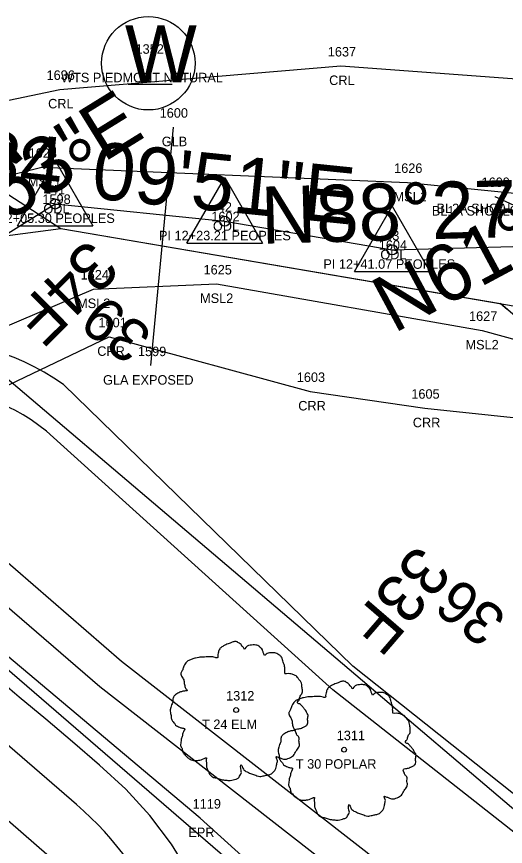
# Model space of a CAD drawing. Extents: x 1812113 to 1819860, y 1177290 to 1181185.
# Drawn here: x 1813798.2 to 1813849.5, y 1178667.1 to 1178754.3 of the extents above; entities that cross this region are included whole.
import ezdxf

# ---------------------------------------------------------------- set-up
doc = ezdxf.new("R2010")
doc.units = 0
for name, color, linetype in [('RD_DTM_BkLn1', 7, 'Continuous'), ('RD_EX_DV_Prop', 7, 'Continuous'), ('RD_EX_H2O', 7, 'Continuous'), ('RD_EX_H2O_txCode', 7, 'Continuous'), ('RD_EX_Misc', 7, 'Continuous'), ('RD_EX_Misc_txCode', 7, 'Continuous'), ('RD_EX_Road', 7, 'Continuous'), ('RD_EX_Road_txCode', 7, 'Continuous'), ('RD_EX_RW', 7, 'Continuous'), ('RD_EX_UT', 7, 'Continuous'), ('RD_EX_UT_txCode', 7, 'Continuous'), ('RD_EX_VEG', 7, 'Continuous'), ('RD_EX_VEG_txCode', 7, 'Continuous'), ('RD_HC_CL', 7, 'Continuous'), ('RD_HC_Data', 7, 'Continuous'), ('RD_HC_txCode', 7, 'Continuous'), ('RD_PD_ALT1_LnLine', 7, 'Continuous'), ('RD_PD_ALT1_TnTmp', 7, 'Continuous'), ('RD_PD_ALT1_TrvlWay', 7, 'Continuous'), ('RD_PD_CstnLmt', 7, 'Continuous'), ('RD_PD_DR_ErosCtrl', 7, 'Continuous'), ('RD_PD_GR', 7, 'Continuous'), ('RD_PD_PatLn1', 7, 'Continuous'), ('RD_PD_RW', 7, 'Continuous'), ('RD_Sketch7', 7, 'Continuous'), ('RD_SMD_Locator', 7, 'Continuous'), ('RD_SMD_Misc', 7, 'Continuous')]:
    doc.layers.add(name, color=color, linetype=linetype)

msp = doc.modelspace()

# ---------------------------------------------------------------- linework, layer by layer
at = {"layer": 'RD_DTM_BkLn1'}
msp.add_line((1813848.444, 1178735.384), (1813869.763, 1178725.59), dxfattribs=at)
at = {"layer": 'RD_EX_DV_Prop'}
for p, q in [((1813781.836, 1178729.192), (1813802.812, 1178732.04)), ((1813802.812, 1178732.04), (1813850.785, 1178723.835)), ((1813854.673, 1178667.319), (1813781.836, 1178729.192))]:
    msp.add_line(p, q, dxfattribs=at)
at = {"layer": 'RD_EX_H2O'}
for points in [[(1813767.831, 1178739.336), (1813802.696, 1178746.648), (1813832.241, 1178749.109), (1813880.122, 1178745.593), (1813913.043, 1178737.891)], [(1813747.032, 1178677.406), (1813754.345, 1178684.796), (1813763.952, 1178688.126), (1813782.123, 1178708.315), (1813807.886, 1178720.632), (1813829.016, 1178714.89), (1813841.058, 1178713.127), (1813882.921, 1178708.729), (1813906.373, 1178716.286)]]:
    msp.add_lwpolyline(points, dxfattribs=at)
at = {"layer": 'RD_EX_Misc'}
for points in [[(1813573.261, 1178698.609), (1813581.176, 1178685.417), (1813588.271, 1178683.03), (1813621.867, 1178683.405), (1813652.093, 1178681.47), (1813685.623, 1178688.184), (1813723.849, 1178690.459), (1813735.911, 1178692.91), (1813768.219, 1178723.128), (1813784.539, 1178734.4), (1813800.789, 1178738.457), (1813839.236, 1178736.87), (1813863.895, 1178734.392), (1813884.494, 1178732.558), (1813903.275, 1178733.231)], [(1813591.145, 1178668.772), (1813628.984, 1178667.844), (1813655.761, 1178668.83), (1813686.954, 1178670.41), (1813726.51, 1178669.36), (1813738.941, 1178670.711), (1813788.676, 1178718.193), (1813806.253, 1178725.658), (1813819.179, 1178726.191), (1813847.084, 1178721.307), (1813860.38, 1178717.648), (1813871.967, 1178724.247), (1813883.921, 1178723.481), (1813902.674, 1178722.415)]]:
    msp.add_lwpolyline(points, dxfattribs=at)
at = {"layer": 'RD_EX_Road'}
msp.add_lwpolyline([(1814076.449, 1178427.399), (1814038.861, 1178461.867), (1814001.829, 1178496.617), (1813965.148, 1178531.537), (1813928.085, 1178567.095), (1813892.01, 1178601.225), (1813854.538, 1178636.515), (1813817.438, 1178670.033), (1813779.867, 1178701.638)], dxfattribs=at)
at = {"layer": 'RD_EX_RW'}
msp.add_line((1813768.43, 1178754.211), (1813802.812, 1178732.04), dxfattribs=at)
at = {"layer": 'RD_EX_UT'}
for p, q in [((1813809.873, 1178747.186), (1813814.502, 1178747.186)), ((1813812.259, 1178717.603), (1813814.643, 1178742.673))]:
    msp.add_line(p, q, dxfattribs=at)
msp.add_circle((1813812.001, 1178749.394), 4.908, dxfattribs=at)
at = {"layer": 'RD_EX_VEG'}
for centre, radius in [((1813821.238, 1178681.396), 0.25), ((1813821.225, 1178681.377), 0.0001), ((1813832.586, 1178677.226), 0.25), ((1813832.574, 1178677.207), 0.0001)]:
    msp.add_circle(centre, radius, dxfattribs=at)
for points in [[(1813821.37, 1178688.563), (1813821.07, 1178688.588), (1813820.745, 1178688.488), (1813820.495, 1178688.388), (1813820.27, 1178688.313), (1813820.045, 1178688.213), (1813819.745, 1178688.038), (1813819.52, 1178687.838), (1813819.395, 1178687.588), (1813819.345, 1178687.363), (1813819.295, 1178687.088), (1813819.295, 1178686.913), (1813819.171, 1178686.888), (1813819.021, 1178686.913), (1813818.771, 1178686.988), (1813818.521, 1178686.988), (1813818.271, 1178686.988), (1813817.921, 1178686.963), (1813817.571, 1178686.963), (1813817.296, 1178686.913), (1813816.971, 1178686.864), (1813816.597, 1178686.739), (1813816.247, 1178686.614), (1813815.947, 1178686.364), (1813815.697, 1178685.889), (1813815.572, 1178685.539), (1813815.422, 1178685.289), (1813815.572, 1178684.839), (1813815.747, 1178684.49), (1813815.772, 1178684.29), (1813815.847, 1178683.865), (1813815.947, 1178683.64), (1813816.072, 1178683.44), (1813815.997, 1178683.415), (1813815.622, 1178683.365), (1813815.322, 1178683.265), (1813814.897, 1178683.04), (1813814.672, 1178682.815), (1813814.572, 1178682.49), (1813814.548, 1178682.141), (1813814.448, 1178681.941), (1813814.373, 1178681.666), (1813814.348, 1178681.591), (1813814.298, 1178681.266), (1813814.398, 1178680.816), (1813814.423, 1178680.466), (1813814.548, 1178680.241), (1813814.697, 1178680.067), (1813814.872, 1178679.817), (1813815.272, 1178679.592), (1813815.597, 1178679.492), (1813815.797, 1178679.467), (1813815.622, 1178678.967), (1813815.572, 1178678.617), (1813815.447, 1178678.217), (1813815.447, 1178678.142), (1813815.397, 1178677.668), (1813815.547, 1178677.343), (1813815.622, 1178676.968), (1813815.797, 1178676.743), (1813816.072, 1178676.443), (1813816.397, 1178676.218), (1813816.897, 1178676.093), (1813817.296, 1178676.118), (1813817.871, 1178676.293), (1813818.121, 1178676.368), (1813818.096, 1178676.193), (1813818.121, 1178675.818), (1813818.121, 1178675.394), (1813818.271, 1178675.069), (1813818.371, 1178674.794), (1813818.521, 1178674.544), (1813818.846, 1178674.319), (1813819.245, 1178674.244), (1813819.67, 1178674.094), (1813820.12, 1178674.019), (1813820.62, 1178673.994), (1813821.22, 1178674.144), (1813821.494, 1178674.269), (1813821.594, 1178674.444), (1813821.794, 1178674.819), (1813821.744, 1178675.044), (1813821.769, 1178675.643), (1813821.869, 1178675.468), (1813822.044, 1178675.119), (1813822.544, 1178674.819), (1813822.944, 1178674.644), (1813823.419, 1178674.494), (1813823.719, 1178674.419), (1813824.193, 1178674.494), (1813824.568, 1178674.569), (1813824.943, 1178674.694), (1813825.243, 1178674.969), (1813825.418, 1178675.244), (1813825.468, 1178675.518), (1813825.543, 1178675.893), (1813825.593, 1178676.068)], [(1813825.593, 1178676.068), (1813825.518, 1178676.243), (1813825.468, 1178676.493), (1813825.543, 1178676.468), (1813825.718, 1178676.418), (1813825.993, 1178676.293), (1813826.217, 1178676.218), (1813826.542, 1178676.243), (1813826.817, 1178676.343), (1813827.267, 1178676.618), (1813827.542, 1178677.093), (1813827.817, 1178677.493), (1813827.892, 1178677.817), (1813827.842, 1178678.042), (1813827.817, 1178678.542), (1813827.617, 1178678.792), (1813827.567, 1178678.917), (1813827.467, 1178679.317), (1813827.542, 1178679.367), (1813827.817, 1178679.417), (1813828.192, 1178679.542), (1813828.466, 1178679.667), (1813828.691, 1178679.842), (1813828.766, 1178680.067), (1813828.741, 1178680.466), (1813828.791, 1178680.866), (1813828.716, 1178681.016), (1813828.616, 1178681.166), (1813828.541, 1178681.366), (1813828.391, 1178681.516), (1813828.292, 1178681.666), (1813828.192, 1178681.766), (1813828.067, 1178681.916), (1813827.892, 1178682.041), (1813827.742, 1178682.091), (1813827.692, 1178682.241), (1813827.842, 1178682.44), (1813827.892, 1178682.54), (1813827.917, 1178682.765), (1813828.142, 1178683.115), (1813828.192, 1178683.515), (1813828.142, 1178683.94), (1813828.092, 1178684.215), (1813827.942, 1178684.49), (1813827.742, 1178684.739), (1813827.617, 1178684.914), (1813827.442, 1178685.039), (1813827.117, 1178685.164), (1813826.867, 1178685.214), (1813826.517, 1178685.214), (1813826.317, 1178685.264), (1813826.342, 1178685.314), (1813826.342, 1178685.464), (1813826.342, 1178685.739), (1813826.267, 1178686.189), (1813826.117, 1178686.689), (1813826.117, 1178686.714), (1813826.017, 1178686.963), (1813825.793, 1178687.163), (1813825.618, 1178687.263), (1813825.418, 1178687.388), (1813825.168, 1178687.413), (1813824.868, 1178687.413), (1813824.593, 1178687.363), (1813824.393, 1178687.263), (1813824.218, 1178687.138), (1813824.143, 1178687.288), (1813824.043, 1178687.588), (1813823.993, 1178687.738), (1813823.843, 1178687.913), (1813823.619, 1178688.113), (1813823.169, 1178688.238), (1813822.544, 1178688.163), (1813822.244, 1178687.963), (1813822.094, 1178687.788), (1813822.044, 1178687.913), (1813821.844, 1178688.113), (1813821.744, 1178688.288), (1813821.569, 1178688.413), (1813821.42, 1178688.513), (1813821.32, 1178688.563)], [(1813832.718, 1178684.393), (1813832.418, 1178684.418), (1813832.094, 1178684.318), (1813831.844, 1178684.218), (1813831.619, 1178684.143), (1813831.394, 1178684.043), (1813831.094, 1178683.868), (1813830.869, 1178683.668), (1813830.744, 1178683.418), (1813830.694, 1178683.193), (1813830.644, 1178682.918), (1813830.644, 1178682.743), (1813830.519, 1178682.718), (1813830.369, 1178682.743), (1813830.119, 1178682.818), (1813829.869, 1178682.818), (1813829.62, 1178682.818), (1813829.27, 1178682.793), (1813828.92, 1178682.793), (1813828.645, 1178682.743), (1813828.32, 1178682.694), (1813827.945, 1178682.569), (1813827.595, 1178682.444), (1813827.296, 1178682.194), (1813827.046, 1178681.719), (1813826.921, 1178681.369), (1813826.771, 1178681.119), (1813826.921, 1178680.669), (1813827.096, 1178680.32), (1813827.121, 1178680.12), (1813827.196, 1178679.695), (1813827.296, 1178679.47), (1813827.421, 1178679.27), (1813827.346, 1178679.245), (1813826.971, 1178679.195), (1813826.671, 1178679.095), (1813826.246, 1178678.87), (1813826.021, 1178678.645), (1813825.921, 1178678.32), (1813825.896, 1178677.971), (1813825.796, 1178677.771), (1813825.721, 1178677.496), (1813825.696, 1178677.421), (1813825.646, 1178677.096), (1813825.746, 1178676.646), (1813825.771, 1178676.296), (1813825.896, 1178676.071), (1813826.046, 1178675.897), (1813826.221, 1178675.647), (1813826.621, 1178675.422), (1813826.946, 1178675.322), (1813827.146, 1178675.297), (1813826.971, 1178674.797), (1813826.921, 1178674.447), (1813826.796, 1178674.047), (1813826.796, 1178673.972), (1813826.746, 1178673.498), (1813826.896, 1178673.173), (1813826.971, 1178672.798), (1813827.146, 1178672.573), (1813827.421, 1178672.273), (1813827.745, 1178672.048), (1813828.245, 1178671.923), (1813828.645, 1178671.948), (1813829.22, 1178672.123), (1813829.47, 1178672.198), (1813829.445, 1178672.023), (1813829.47, 1178671.648), (1813829.47, 1178671.224), (1813829.62, 1178670.899), (1813829.72, 1178670.624), (1813829.869, 1178670.374), (1813830.194, 1178670.149), (1813830.594, 1178670.074), (1813831.019, 1178669.924), (1813831.469, 1178669.849), (1813831.969, 1178669.824), (1813832.568, 1178669.974), (1813832.843, 1178670.099), (1813832.943, 1178670.274), (1813833.143, 1178670.649), (1813833.093, 1178670.874), (1813833.118, 1178671.473), (1813833.218, 1178671.298), (1813833.393, 1178670.949), (1813833.893, 1178670.649), (1813834.293, 1178670.474), (1813834.767, 1178670.324), (1813835.067, 1178670.249), (1813835.542, 1178670.324), (1813835.917, 1178670.399), (1813836.292, 1178670.524), (1813836.592, 1178670.799), (1813836.766, 1178671.074), (1813836.816, 1178671.348), (1813836.891, 1178671.723), (1813836.941, 1178671.898)], [(1813836.941, 1178671.898), (1813836.866, 1178672.073), (1813836.816, 1178672.323), (1813836.891, 1178672.298), (1813837.066, 1178672.248), (1813837.341, 1178672.123), (1813837.566, 1178672.048), (1813837.891, 1178672.073), (1813838.166, 1178672.173), (1813838.616, 1178672.448), (1813838.891, 1178672.923), (1813839.165, 1178673.323), (1813839.24, 1178673.647), (1813839.19, 1178673.872), (1813839.165, 1178674.372), (1813838.965, 1178674.622), (1813838.915, 1178674.747), (1813838.816, 1178675.147), (1813838.891, 1178675.197), (1813839.165, 1178675.247), (1813839.54, 1178675.372), (1813839.815, 1178675.497), (1813840.04, 1178675.672), (1813840.115, 1178675.897), (1813840.09, 1178676.296), (1813840.14, 1178676.696), (1813840.065, 1178676.846), (1813839.965, 1178676.996), (1813839.89, 1178677.196), (1813839.74, 1178677.346), (1813839.64, 1178677.496), (1813839.54, 1178677.596), (1813839.415, 1178677.746), (1813839.24, 1178677.871), (1813839.09, 1178677.921), (1813839.04, 1178678.071), (1813839.19, 1178678.27), (1813839.24, 1178678.37), (1813839.265, 1178678.595), (1813839.49, 1178678.945), (1813839.54, 1178679.345), (1813839.49, 1178679.77), (1813839.44, 1178680.045), (1813839.29, 1178680.32), (1813839.09, 1178680.569), (1813838.965, 1178680.744), (1813838.791, 1178680.869), (1813838.466, 1178680.994), (1813838.216, 1178681.044), (1813837.866, 1178681.044), (1813837.666, 1178681.094), (1813837.691, 1178681.144), (1813837.691, 1178681.294), (1813837.691, 1178681.569), (1813837.616, 1178682.019), (1813837.466, 1178682.519), (1813837.466, 1178682.544), (1813837.366, 1178682.793), (1813837.141, 1178682.993), (1813836.966, 1178683.093), (1813836.766, 1178683.218), (1813836.517, 1178683.243), (1813836.217, 1178683.243), (1813835.942, 1178683.193), (1813835.742, 1178683.093), (1813835.567, 1178682.968), (1813835.492, 1178683.118), (1813835.392, 1178683.418), (1813835.342, 1178683.568), (1813835.192, 1178683.743), (1813834.967, 1178683.943), (1813834.517, 1178684.068), (1813833.893, 1178683.993), (1813833.593, 1178683.793), (1813833.443, 1178683.618), (1813833.393, 1178683.743), (1813833.193, 1178683.943), (1813833.093, 1178684.118), (1813832.918, 1178684.243), (1813832.768, 1178684.343), (1813832.668, 1178684.393)]]:
    msp.add_spline(points, degree=3, dxfattribs=at)
at = {"layer": 'RD_HC_CL'}
for p, q in [((1813785.202, 1178724.075), (1813802.213, 1178734.602)), ((1813802.213, 1178734.602), (1813820.035, 1178732.781)), ((1813820.035, 1178732.781), (1813837.634, 1178729.785)), ((1813837.634, 1178729.785), (1813857.382, 1178730.318)), ((1813850.516, 1178623.797), (1813755.38, 1178705.862))]:
    msp.add_line(p, q, dxfattribs=at)
at = {"layer": 'RD_HC_Data'}
for p, q in [((1813798.242, 1178732.31), (1813802.214, 1178739.189)), ((1813802.214, 1178739.189), (1813806.183, 1178732.31)), ((1813816.064, 1178730.488), (1813820.036, 1178737.368)), ((1813820.036, 1178737.368), (1813824.004, 1178730.488)), ((1813833.664, 1178727.492), (1813837.636, 1178734.372)), ((1813837.636, 1178734.372), (1813841.604, 1178727.492)), ((1813798.242, 1178732.31), (1813806.183, 1178732.31)), ((1813816.064, 1178730.488), (1813824.004, 1178730.488)), ((1813833.664, 1178727.492), (1813841.604, 1178727.492))]:
    msp.add_line(p, q, dxfattribs=at)
for centre in [(1813802.213, 1178734.602), (1813820.035, 1178732.781), (1813837.634, 1178729.785)]:
    msp.add_circle(centre, 0.529, dxfattribs=at)
at = {"layer": 'RD_PD_ALT1_LnLine'}
for p, q in [((1813781.836, 1178729.192), (1813802.812, 1178732.04)), ((1813802.812, 1178732.04), (1813849.018, 1178724.137)), ((1813854.673, 1178667.319), (1813781.836, 1178729.192)), ((1813849.018, 1178724.137), (1813849.716, 1178723.535))]:
    msp.add_line(p, q, dxfattribs=at)
at = {"layer": 'RD_PD_ALT1_TrvlWay'}
msp.add_line((1813855.7, 1178635.172), (1813779.98, 1178700.49), dxfattribs=at)
at = {"layer": 'RD_PD_CstnLmt'}
for p, q in [((1813831.386, 1178683.534), (1813802.048, 1178710.053)), ((1813870.713, 1178652.576), (1813831.386, 1178683.534))]:
    msp.add_line(p, q, dxfattribs=at)
msp.add_arc((1813788.637, 1178695.216), 20, 47.88964, 139.21843, dxfattribs=at)
at = {"layer": 'RD_PD_DR_ErosCtrl'}
for p, q in [((1813833.516, 1178686.004), (1813803.068, 1178715.63)), ((1813872.683, 1178654.86), (1813833.516, 1178686.004))]:
    msp.add_line(p, q, dxfattribs=at)
msp.add_arc((1813788.637, 1178695.216), 25, 54.74185, 139.21843, dxfattribs=at)
at = {"layer": 'RD_PD_GR'}
for p, q in [((1813783.246, 1178704.276), (1813806.909, 1178683.864)), ((1813806.909, 1178683.864), (1813846.352, 1178653.136))]:
    msp.add_line(p, q, dxfattribs=at)
at = {"layer": 'RD_PD_PatLn1'}
for p, q in [((1813809.195, 1178686.515), (1813785.532, 1178706.926)), ((1813848.639, 1178655.787), (1813809.195, 1178686.515))]:
    msp.add_line(p, q, dxfattribs=at)
at = {"layer": 'RD_PD_RW'}
msp.add_line((1813877.921, 1178699.206), (1813849.018, 1178724.137), dxfattribs=at)
at = {"layer": 'RD_Sketch7'}
msp.add_line((1813804.452, 1178671.456), (1813759.299, 1178710.406), dxfattribs=at)
msp.add_lwpolyline([(1813816.387, 1178664.101), (1813814.425, 1178667.296), (1813812.168, 1178670.297), (1813809.633, 1178673.074), (1813806.855, 1178675.611), (1813804.027, 1178678.042), (1813801.221, 1178680.423), (1813798.44, 1178682.762), (1813795.686, 1178685.068)], dxfattribs=at)
msp.add_arc((1813781.591, 1178644.954), 35, 303.51678, 49.21843, dxfattribs=at)
at = {"layer": 'RD_SMD_Locator'}
for centre in [(1813832.241, 1178749.109), (1813802.696, 1178746.648), (1813814.643, 1178742.673), (1813800.789, 1178738.457), (1813839.236, 1178736.87), (1813848.444, 1178735.384), (1813802.213, 1178734.602), (1813802.213, 1178734.602), (1813820.035, 1178732.781), (1813820.035, 1178732.781), (1813837.634, 1178729.785), (1813837.634, 1178729.785), (1813806.253, 1178725.658), (1813819.179, 1178726.191), (1813847.084, 1178721.307), (1813807.886, 1178720.632), (1813812.259, 1178717.603), (1813829.016, 1178714.89), (1813841.058, 1178713.127), (1813817.438, 1178670.033)]:
    msp.add_circle(centre, 0.001, dxfattribs=at)

# ---------------------------------------------------------------- texts
at = {"layer": 'RD_EX_H2O_txCode'}
for s, p in [('1637', (1813830.87, 1178750.109)), ('1636', (1813801.303, 1178747.648)), ('CRL', (1813831.012, 1178747.109)), ('CRL', (1813801.468, 1178744.648)), ('1598', (1813800.867, 1178734.602)), ('ODL', (1813800.969, 1178733.602)), ('1602', (1813818.625, 1178732.781)), ('ODL', (1813818.79, 1178731.781)), ('1604', (1813836.225, 1178729.785)), ('ODL', (1813836.39, 1178728.785)), ('1601', (1813806.76, 1178721.632)), ('CRR', (1813806.634, 1178718.632)), ('1603', (1813827.607, 1178715.89)), ('1605', (1813839.649, 1178714.127)), ('CRR', (1813827.764, 1178712.89)), ('CRR', (1813839.806, 1178711.127))]:
    msp.add_text(s, height=1, dxfattribs=at).set_placement(p)
at = {"layer": 'RD_EX_Misc_txCode'}
for s, p in [('1623', (1813799.419, 1178739.457)), ('1626', (1813837.842, 1178737.87)), ('MSL1', (1813799.333, 1178736.457)), ('MSL1', (1813837.779, 1178734.87)), ('1624', (1813804.883, 1178726.658)), ('1625', (1813817.809, 1178727.191)), ('MSL2', (1813817.439, 1178724.191)), ('MSL2', (1813804.513, 1178723.658)), ('1627', (1813845.714, 1178722.307)), ('MSL2', (1813845.344, 1178719.307))]:
    msp.add_text(s, height=1, dxfattribs=at).set_placement(p)
at = {"layer": 'RD_EX_Road_txCode'}
for s, p in [('1119', (1813816.659, 1178671.033)), ('EPR', (1813816.21, 1178668.033))]:
    msp.add_text(s, height=1, dxfattribs=at).set_placement(p)
at = {"layer": 'RD_EX_UT'}
msp.add_text('W', height=6, dxfattribs=at).set_placement((1813809.537, 1178747.393))
at = {"layer": 'RD_EX_UT_txCode'}
for s, p in [('1352', (1813810.655, 1178750.394)), ('WTS PIEDMONT NATURAL', (1813802.828, 1178747.394)), ('1600', (1813813.194, 1178743.673)), ('GLB', (1813813.414, 1178740.673)), ('1599', (1813810.912, 1178718.603)), ('GLA EXPOSED', (1813807.243, 1178715.603))]:
    msp.add_text(s, height=1, dxfattribs=at).set_placement(p)
at = {"layer": 'RD_EX_VEG_txCode'}
for s, p in [('1312', (1813820.175, 1178682.396)), ('T 24 ELM', (1813817.647, 1178679.396)), ('1311', (1813831.807, 1178678.226)), ('T 30 POPLAR', (1813827.508, 1178675.226))]:
    msp.add_text(s, height=1, dxfattribs=at).set_placement(p)
at = {"layer": 'RD_HC_txCode'}
for s, p in [('41', (1813801.764, 1178735.602)), ('42', (1813819.302, 1178733.781)), ('PI 12+05.30 PEOPLES', (1813794.615, 1178732.602)), ('PI 12+23.21 PEOPLES', (1813813.121, 1178730.781)), ('43', (1813836.902, 1178730.785)), ('PI 12+41.07 PEOPLES', (1813830.398, 1178727.785))]:
    msp.add_text(s, height=1, dxfattribs=at).set_placement(p)
at = {"layer": 'RD_PD_ALT1_TnTmp'}
for s, rotation, p in [('N61%%d46\'05"E', 28.23186, (1813837.794, 1178720.936)), ('N58%%d14\'53"E', 31.75204, (1813773.138, 1178717.785)), ('N47%%d21\'19"E', 218.97815, (1813795.54, 1178744.441)), ('S84%%d09\'51"E', 354.16418, (1813788.509, 1178737.008)), ('N88%%d27\'11"E', 1.54697, (1813823.918, 1178730.415))]:
    msp.add_text(s, height=6, rotation=rotation, dxfattribs=at).set_placement(p)
at = {"layer": 'RD_PD_CstnLmt'}
for s, rotation, p in [('34F', 224.80482, (1813805.725, 1178731.094)), ('33F', 229.22663, (1813840.343, 1178698.976))]:
    msp.add_text(s, height=5, rotation=rotation, dxfattribs=at).set_placement(p)
at = {"layer": 'RD_PD_DR_ErosCtrl'}
for s, p in [('39', (1813812.634, 1178721.08)), ('36', (1813849.887, 1178691.323))]:
    msp.add_text(s, height=4.5, rotation=141.98143, dxfattribs=at).set_placement(p)
at = {"layer": 'RD_SMD_Misc'}
for s, p in [('1609', (1813847.034, 1178736.384)), ('BL1A SHOALS TOP', (1813841.806, 1178733.384)), ('BL2A SHOALS BOTTOM', (1813842.303, 1178733.637))]:
    msp.add_text(s, height=1, dxfattribs=at).set_placement(p)

doc.saveas('drawing.dxf')
